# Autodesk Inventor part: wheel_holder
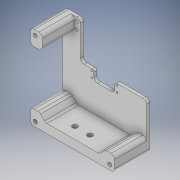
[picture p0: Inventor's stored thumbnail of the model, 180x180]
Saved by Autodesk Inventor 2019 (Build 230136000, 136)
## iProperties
Created: 2018-06
Part Number: wheel_holder
Material: Generic
Document SubType Name: Modeling
Designer: felldings
Density: 1 g/cm^3
Appearance: Default
Author: felldings
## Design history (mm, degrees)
sketch "Sketch8"
  geometry: L1 (0, 0)-(140, 0); L2 (140, 0)-(140, 78); L3 (140, 78)-(87.5, 78); L4 (87.5, 78)-(87.5, 62); L5 (87.5, 62)-(52.5, 62); L6 (52.5, 62)-(52.5, 78); L7 (52.5, 78)-(30, 78); L8 (30, 78)-(30, 140); L9 (30, 140)-(0, 140); L10 (0, 140)-(0, 0); 1 further point
  constraints: 20 end point, 8 perpendicular, 2 point on line, 1 horizontal
  dimensions: "d55" = 70 distance from line of L10 point (70, 70); "d56" = 70 distance from line of L1 point (70, 70); "d57" = 8 distance from line of L5 point (70, 70); "d58" = 16 distance of L5.end L6.end; "d59" = 35 distance of L4.end L5.end; "d60" = 17.5 distance from line of point (70, 70) L6; "d61" = 40 distance from line of point (70, 70) L8; "d62" = 140 distance between parallel lines of L1 L9; "d63" = 140 distance of L1.start L1.end
extrude "base_plate" new body sketch "Sketch8" distance "d64" = 5; taper "d65" = 0 deg
sketch "Sketch9"
  geometry: L1 (52.5, 62)-(52.5, 78) reference; L2 (0, 0)-(140, 0) reference; 4 further points
  dimensions: "d66" = 42 distance of point (91, 65) point (49, 65); "d67" = 42 distance of point (91, 75) point (49, 75); "d68" = 10 distance of point (49, 65) point (49, 75); "d69" = 10 distance of point (91, 65) point (91, 75); "d70" = 3.5 distance from line of L1 point (49, 75); "d71" = 3.5 distance from line of L1 point (49, 65); "d72" = 65 distance from line of L2 point (91, 65); "d73" = 65 distance from line of L2 point (49, 65)
hole "pcb_mount_holes" sketch "Sketch9" at (49, 75), (49, 65), (91, 75), (91, 65) diameter "d74" = 3; stored, may be unused: countersink angle "d78" = 90 deg, drill point angle "d80" = 118 deg; dims "d75" = 6, "d76" = 4, "d77" = 2, "d79" = 8
sketch "Sketch10"
  geometry: L1 (0, 0)-(25, 0); L2 (25, 0)-(25, 25); L3 (25, 25)-(0, 25); L4 (0, 25)-(0, 0); L5 (0, 0)-(140, 0) reference; L6 (140, 0)-(115, 0); L7 (115, 0)-(115, 25); L8 (115, 25)-(140, 25); L9 (140, 25)-(140, 0); L10 (0, 140)-(0, 0) reference; L11 (0, 140)-(20, 140); L12 (20, 140)-(20, 115); L13 (20, 115)-(0, 115); L14 (0, 115)-(0, 140); C1 r 65 at (70, 70)
  constraints: 24 end point, 6 parallel, 3 horizontal, 3 perpendicular, 1 centre point
  dimensions: "d81" = 130 diameter of C1; "d82" = 20 distance of L12.end L13.end; "d83" = 25 distance of L11.end L12.end; "d84" = 25 distance of L2.end L3.end; "d85" = 25 distance of L1.end L2.end; "d86" = 25 distance of L6.end L7.end; "d87" = 25 distance of L7.end L8.end
extrude "distance_blocks" join sketch "Sketch10" distance "d88" = 53; taper "d89" = 0 deg
chamfer "space_for_digitwheel" distance "d90" = 10; stored, may be unused: second distance "d91" = 2, angle "d92" = 45 deg
chamfer "space_for_digitwheel2" distance "d93" = 5; stored, may be unused: second distance "d94" = 2, angle "d95" = 45 deg
sketch "Sketch11"
  geometry: L1 (30, 78)-(30, 140) reference; L2 (30, 140)-(20, 140) reference; 3 further points
  dimensions: "d96" = 6 distance from line of L1 point (24, 134); "d97" = 6 distance from line of L1 point (24, 122); "d98" = 6 distance from line of L2 point (24, 134); "d99" = 12 distance of point (24, 134) point (24, 122)
hole "cable_fixation_holes" sketch "Sketch11" at (24, 134), (24, 122) diameter "d100" = 5; stored, may be unused: countersink angle "d104" = 90 deg, drill point angle "d106" = 118 deg; dims "d101" = 6, "d102" = 4, "d103" = 2, "d105" = 8
sketch "Sketch12"
  geometry: L1 (0, 0)-(140, 0) reference; L2 (125, 25)-(115, 15) reference; L3 (25, 0)-(115, 0); L4 (115, 0)-(115, 15); L5 (115, 15)-(25, 15); L6 (25, 15)-(25, 0); L7 (25, 15)-(25, 0) reference
  constraints: 8 end point, 2 parallel, 1 collinear, 1 horizontal, 1 perpendicular, 1 point on line
extrude "lighting space" join sketch "Sketch12" distance "d107" = 53; taper "d108" = 0 deg
sketch "Sketch13"
  geometry: L1 (0, 140)-(0, 0) reference; L2 (0, 0)-(-140, 0) reference; L3 (0, 0)-(-140, 0) reference; L4 (-140, 0)-(-140, 78) reference; L5 (-30, 140)-(0, 140) reference; 5 further points
  dimensions: "d109" = 8 distance from line of L1 point (-8, 8); "d110" = 8 distance from line of L2 point (-8, 8); "d111" = 8 distance from line of L3 point (-132, 8); "d112" = 8 distance from line of L4 point (-132, 8); "d113" = 8 distance from line of L5 point (-8, 132); "d114" = 8 distance from line of L1 point (-8, 132)
hole "grouping_holes" sketch "Sketch13" at (-8, 8), (-8, 132), (-132, 8) diameter "d115" = 6.5; stored, may be unused: countersink angle "d119" = 90 deg, drill point angle "d121" = 118 deg; dims "d116" = 6, "d117" = 4, "d118" = 2, "d120" = 8
fillet "Fillet5" dims "d123" = 6
fillet "Fillet6" dims "d124" = 6
fillet "Fillet7" dims "d125" = 3
sketch "Sketch14"
  geometry: L1 (0, 128)-(0, 0) reference; L2 (0, -6)-(58, -6) reference; 2 further points
  dimensions: "d126" = 29 distance from line of L1 point (29, 118); "d127" = 29 distance from line of L1 point (29, 10); "d128" = 108 distance of point (29, 10) point (29, 118); "d129" = 16 distance from line of L2 point (29, 10)
hole "footholes" sketch "Sketch14" at (29, 118), (29, 10) diameter "d130" = 4.5; stored, may be unused: countersink angle "d134" = 90 deg, drill point angle "d136" = 118 deg; dims "d131" = 6, "d132" = 4, "d133" = 2, "d135" = 8
sketch "Sketch15"
  geometry: L1 (0, 0)-(128, 0) reference; L2 (49, 39)-(74, 39); 1 further point
  constraints: 2 end point, 1 horizontal
  dimensions: "d137" = 39 distance from line of L1 L2.start; "d138" = 25 distance of L2.start L2.end; "d139" = 55 horizontal distance of point (-6, 0) L2.start
hole "frontplate_holes" sketch "Sketch15" at (49, 39), (74, 39) diameter "d140" = 8.5; stored, may be unused: countersink angle "d144" = 90 deg, drill point angle "d146" = 0 deg; dims "d141" = 6, "d142" = 4, "d143" = 2, "d145" = 2.5
body "Solid3"
